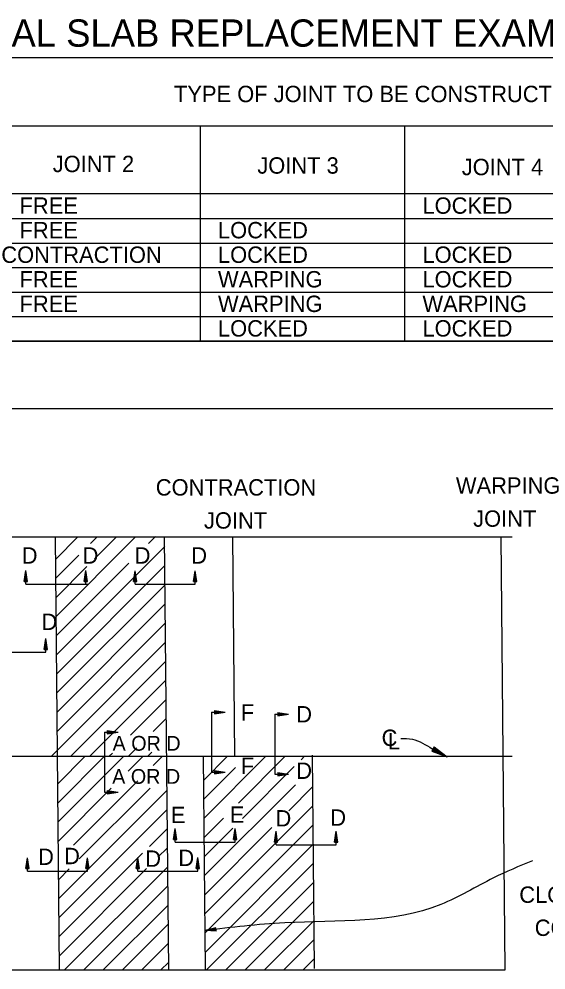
# Model space of a CAD drawing. Extents: x 1375738 to 1375905, y 380661 to 380875.
# Drawn here: x 1375824.96 to 1375840.42, y 380818.56 to 380846.45 of the extents above; entities that cross this region are included whole.
import ezdxf

# ---------------------------------------------------------------- set-up
doc = ezdxf.new("R2010")
doc.units = 0
doc.layers.add('R_Border', color=7, linetype='Continuous')
doc.layers.add('R_Draft', color=7, linetype='Continuous')

msp = doc.modelspace()

# ---------------------------------------------------------------- linework, layer by layer
at = {"layer": 'R_Border'}
msp.add_line((1375786.095, 380835.027), (1375854.78, 380835.027), dxfattribs=at)
at = {"layer": 'R_Draft'}
for p, q in [((1375810.272, 380845.32), (1375854.272, 380845.32)), ((1375818.272, 380843.319), (1375854.272, 380843.319)), ((1375830.272, 380843.319), (1375830.272, 380841.32)), ((1375836.272, 380843.319), (1375836.272, 380841.32)), ((1375830.272, 380841.32), (1375824.272, 380841.32)), ((1375836.272, 380841.32), (1375830.272, 380841.32)), ((1375830.272, 380841.32), (1375830.272, 380840.6)), ((1375842.272, 380841.32), (1375836.272, 380841.32)), ((1375836.272, 380841.32), (1375836.272, 380840.6)), ((1375824.272, 380840.6), (1375830.272, 380840.6)), ((1375830.272, 380840.6), (1375836.272, 380840.6)), ((1375830.272, 380840.6), (1375830.272, 380839.88)), ((1375836.272, 380840.6), (1375836.272, 380839.88)), ((1375836.272, 380840.6), (1375842.272, 380840.6)), ((1375824.272, 380839.88), (1375830.272, 380839.88)), ((1375830.272, 380839.88), (1375830.272, 380839.16)), ((1375830.272, 380839.88), (1375836.272, 380839.88)), ((1375836.272, 380839.88), (1375842.272, 380839.88)), ((1375836.272, 380839.88), (1375836.272, 380839.16)), ((1375824.272, 380839.16), (1375830.272, 380839.16)), ((1375830.272, 380839.16), (1375836.272, 380839.16)), ((1375830.272, 380839.16), (1375830.272, 380838.44)), ((1375836.272, 380839.16), (1375836.272, 380838.44)), ((1375836.272, 380839.16), (1375842.272, 380839.16)), ((1375824.272, 380838.44), (1375830.272, 380838.44)), ((1375830.272, 380838.44), (1375836.272, 380838.44)), ((1375830.272, 380838.44), (1375830.272, 380837.72)), ((1375836.272, 380838.44), (1375836.272, 380837.72)), ((1375836.272, 380838.44), (1375842.272, 380838.44)), ((1375824.272, 380837.72), (1375830.272, 380837.72)), ((1375830.272, 380837.72), (1375830.272, 380837)), ((1375830.272, 380837.72), (1375836.272, 380837.72)), ((1375836.272, 380837.72), (1375836.272, 380837)), ((1375836.272, 380837.72), (1375842.272, 380837.72)), ((1375854.272, 380837), (1375810.272, 380837)), ((1375824.272, 380837), (1375830.272, 380837)), ((1375830.272, 380837), (1375836.272, 380837)), ((1375836.272, 380837), (1375842.272, 380837)), ((1375795.429, 380831.261), (1375839.429, 380831.261)), ((1375826.149, 380818.564), (1375826.027, 380831.261)), ((1375826.034, 380830.611), (1375826.683, 380831.261)), ((1375826.05, 380828.93), (1375828.38, 380831.261)), ((1375827.059, 380831.07), (1375827.249, 380831.261)), ((1375827.174, 380830.62), (1375827.815, 380831.261)), ((1375828.753, 380831.067), (1375828.958, 380831.273)), ((1375829.349, 380818.564), (1375829.228, 380831.261)), ((1375831.289, 380824.829), (1375831.228, 380831.261)), ((1375839.223, 380818.564), (1375839.103, 380831.261)), ((1375826.061, 380827.809), (1375829.231, 380830.979)), ((1375826.039, 380830.051), (1375826.714, 380830.725)), ((1375826.055, 380828.37), (1375828.178, 380830.493)), ((1375826.066, 380827.249), (1375829.236, 380830.419)), ((1375825.109, 380829.954), (1375825.157, 380830.274)), ((1375825.117, 380829.954), (1375825.157, 380830.221)), ((1375825.125, 380829.954), (1375825.157, 380830.166)), ((1375825.157, 380829.874), (1375825.157, 380830.274)), ((1375825.205, 380829.954), (1375825.157, 380830.274)), ((1375825.197, 380829.954), (1375825.157, 380830.221)), ((1375825.189, 380829.954), (1375825.157, 380830.166)), ((1375826.044, 380829.49), (1375826.945, 380830.391)), ((1375826.871, 380829.954), (1375826.919, 380830.274)), ((1375826.879, 380829.954), (1375826.919, 380830.221)), ((1375826.887, 380829.954), (1375826.919, 380830.166)), ((1375826.919, 380829.874), (1375826.919, 380830.274)), ((1375826.967, 380829.954), (1375826.919, 380830.274)), ((1375826.959, 380829.954), (1375826.919, 380830.221)), ((1375826.951, 380829.954), (1375826.919, 380830.166)), ((1375828.319, 380829.952), (1375828.367, 380830.272)), ((1375828.327, 380829.952), (1375828.367, 380830.219)), ((1375828.335, 380829.952), (1375828.367, 380830.164)), ((1375828.367, 380829.872), (1375828.367, 380830.272)), ((1375828.415, 380829.952), (1375828.367, 380830.272)), ((1375828.407, 380829.952), (1375828.367, 380830.219)), ((1375828.399, 380829.952), (1375828.367, 380830.164)), ((1375830.081, 380829.952), (1375830.129, 380830.272)), ((1375830.089, 380829.952), (1375830.129, 380830.219)), ((1375830.097, 380829.952), (1375830.129, 380830.164)), ((1375830.129, 380829.872), (1375830.129, 380830.272)), ((1375830.177, 380829.952), (1375830.129, 380830.272)), ((1375830.169, 380829.952), (1375830.129, 380830.219)), ((1375830.161, 380829.952), (1375830.129, 380830.164)), ((1375825.109, 380829.954), (1375825.205, 380829.954)), ((1375825.133, 380829.954), (1375825.157, 380830.113)), ((1375825.141, 380829.954), (1375825.157, 380830.058)), ((1375825.149, 380829.954), (1375825.157, 380830.005)), ((1375825.181, 380829.954), (1375825.157, 380830.113)), ((1375825.173, 380829.954), (1375825.157, 380830.058)), ((1375825.165, 380829.954), (1375825.157, 380830.005)), ((1375825.157, 380829.874), (1375826.994, 380829.874)), ((1375826.071, 380826.688), (1375829.241, 380829.859)), ((1375826.871, 380829.954), (1375826.967, 380829.954)), ((1375826.895, 380829.954), (1375826.919, 380830.113)), ((1375826.903, 380829.954), (1375826.919, 380830.058)), ((1375826.911, 380829.954), (1375826.919, 380830.005)), ((1375826.943, 380829.954), (1375826.919, 380830.113)), ((1375826.934, 380829.954), (1375826.919, 380830.058)), ((1375826.926, 380829.954), (1375826.919, 380830.005)), ((1375828.319, 380829.952), (1375828.415, 380829.952)), ((1375828.343, 380829.952), (1375828.367, 380830.111)), ((1375828.351, 380829.952), (1375828.367, 380830.056)), ((1375828.359, 380829.952), (1375828.367, 380830.003)), ((1375828.391, 380829.952), (1375828.367, 380830.111)), ((1375828.383, 380829.952), (1375828.367, 380830.056)), ((1375828.375, 380829.952), (1375828.367, 380830.003)), ((1375828.367, 380829.872), (1375830.129, 380829.872)), ((1375830.081, 380829.952), (1375830.177, 380829.952)), ((1375830.105, 380829.952), (1375830.129, 380830.111)), ((1375830.113, 380829.952), (1375830.129, 380830.056)), ((1375830.121, 380829.952), (1375830.129, 380830.003)), ((1375830.153, 380829.952), (1375830.129, 380830.111)), ((1375830.144, 380829.952), (1375830.129, 380830.056)), ((1375830.136, 380829.952), (1375830.129, 380830.003)), ((1375826.077, 380826.128), (1375829.247, 380829.298)), ((1375826.082, 380825.568), (1375829.252, 380828.738)), ((1375825.699, 380827.963), (1375825.747, 380828.283)), ((1375825.707, 380827.963), (1375825.747, 380828.229)), ((1375825.715, 380827.963), (1375825.747, 380828.175)), ((1375825.747, 380827.883), (1375825.747, 380828.283)), ((1375825.795, 380827.963), (1375825.747, 380828.283)), ((1375825.787, 380827.963), (1375825.747, 380828.229)), ((1375825.779, 380827.963), (1375825.747, 380828.175)), ((1375825.909, 380824.829), (1375829.257, 380828.178)), ((1375825.699, 380827.963), (1375825.795, 380827.963)), ((1375825.723, 380827.963), (1375825.747, 380828.121)), ((1375825.731, 380827.963), (1375825.747, 380828.067)), ((1375825.739, 380827.963), (1375825.747, 380828.013)), ((1375825.771, 380827.963), (1375825.747, 380828.121)), ((1375825.762, 380827.963), (1375825.747, 380828.067)), ((1375825.754, 380827.963), (1375825.747, 380828.013)), ((1375823.985, 380827.883), (1375825.747, 380827.883)), ((1375826.475, 380824.829), (1375829.263, 380827.617)), ((1375827.04, 380824.829), (1375829.268, 380827.057)), ((1375828.229, 380825.452), (1375829.273, 380826.497)), ((1375830.61, 380826.123), (1375830.61, 380824.361)), ((1375830.61, 380826.123), (1375831.01, 380826.123)), ((1375830.69, 380826.171), (1375831.01, 380826.123)), ((1375830.69, 380826.171), (1375830.69, 380826.075)), ((1375830.69, 380826.163), (1375830.957, 380826.123)), ((1375830.69, 380826.155), (1375830.902, 380826.123)), ((1375830.69, 380826.147), (1375830.849, 380826.123)), ((1375830.69, 380826.138), (1375830.794, 380826.123)), ((1375830.69, 380826.13), (1375830.741, 380826.123)), ((1375830.69, 380826.075), (1375831.01, 380826.123)), ((1375830.69, 380826.107), (1375830.794, 380826.123)), ((1375830.69, 380826.091), (1375830.902, 380826.123)), ((1375830.69, 380826.083), (1375830.957, 380826.123)), ((1375830.69, 380826.099), (1375830.849, 380826.123)), ((1375830.69, 380826.115), (1375830.741, 380826.123)), ((1375832.467, 380826.064), (1375832.467, 380824.302)), ((1375832.467, 380826.064), (1375832.867, 380826.064)), ((1375832.547, 380826.112), (1375832.867, 380826.064)), ((1375832.547, 380826.112), (1375832.547, 380826.016)), ((1375832.547, 380826.104), (1375832.813, 380826.064)), ((1375832.547, 380826.096), (1375832.759, 380826.064)), ((1375832.547, 380826.088), (1375832.705, 380826.064)), ((1375832.547, 380826.079), (1375832.651, 380826.064)), ((1375832.547, 380826.071), (1375832.597, 380826.064)), ((1375832.547, 380826.016), (1375832.867, 380826.064)), ((1375832.547, 380826.048), (1375832.651, 380826.064)), ((1375832.547, 380826.032), (1375832.759, 380826.064)), ((1375832.547, 380826.024), (1375832.813, 380826.064)), ((1375832.547, 380826.04), (1375832.705, 380826.064)), ((1375832.547, 380826.056), (1375832.597, 380826.064)), ((1375828.898, 380825.556), (1375829.279, 380825.937)), ((1375827.465, 380825.539), (1375827.465, 380823.777)), ((1375827.465, 380825.539), (1375827.865, 380825.539)), ((1375827.545, 380825.587), (1375827.865, 380825.539)), ((1375827.545, 380825.587), (1375827.545, 380825.491)), ((1375827.545, 380825.579), (1375827.812, 380825.539)), ((1375827.545, 380825.571), (1375827.757, 380825.539)), ((1375827.545, 380825.563), (1375827.704, 380825.539)), ((1375827.545, 380825.555), (1375827.649, 380825.539)), ((1375827.545, 380825.547), (1375827.596, 380825.539)), ((1375827.545, 380825.491), (1375827.865, 380825.539)), ((1375827.545, 380825.523), (1375827.649, 380825.539)), ((1375827.545, 380825.507), (1375827.757, 380825.539)), ((1375827.545, 380825.499), (1375827.812, 380825.539)), ((1375827.545, 380825.515), (1375827.704, 380825.539)), ((1375827.545, 380825.531), (1375827.596, 380825.539)), ((1375794.677, 380824.829), (1375839.429, 380824.829)), ((1375806.196, 380824.829), (1375839.375, 380824.829)), ((1375826.097, 380824.023), (1375826.903, 380824.829)), ((1375826.102, 380823.463), (1375827.469, 380824.829)), ((1375826.107, 380822.903), (1375828.034, 380824.829)), ((1375827.606, 380824.829), (1375827.696, 380824.92)), ((1375828.162, 380824.391), (1375828.6, 380824.829)), ((1375828.171, 380824.829), (1375828.418, 380825.075)), ((1375828.738, 380824.829), (1375828.857, 380824.949)), ((1375828.894, 380824.558), (1375829.165, 380824.829)), ((1375830.429, 380818.574), (1375830.369, 380824.829)), ((1375830.376, 380824.133), (1375831.072, 380824.829)), ((1375830.387, 380823.013), (1375832.203, 380824.829)), ((1375831.395, 380823.455), (1375832.769, 380824.829)), ((1375833.233, 380824.728), (1375833.335, 380824.829)), ((1375833.629, 380818.605), (1375833.569, 380824.86)), ((1375837.137, 380825.102), (1375837.068, 380824.975)), ((1375837.068, 380824.975), (1375837.524, 380824.809)), ((1375837.074, 380824.986), (1375837.453, 380824.847)), ((1375837.079, 380824.997), (1375837.381, 380824.887)), ((1375837.085, 380825.007), (1375837.311, 380824.925)), ((1375837.091, 380825.018), (1375837.239, 380824.964)), ((1375837.097, 380825.029), (1375837.169, 380825.002)), ((1375837.108, 380825.049), (1375837.169, 380825.002)), ((1375837.113, 380825.059), (1375837.239, 380824.964)), ((1375837.119, 380825.07), (1375837.311, 380824.925)), ((1375837.125, 380825.081), (1375837.381, 380824.887)), ((1375837.131, 380825.091), (1375837.453, 380824.847)), ((1375837.137, 380825.102), (1375837.524, 380824.809)), ((1375830.381, 380823.573), (1375831.309, 380824.501)), ((1375830.61, 380824.361), (1375831.01, 380824.361)), ((1375830.69, 380824.409), (1375831.01, 380824.361)), ((1375830.69, 380824.409), (1375830.69, 380824.313)), ((1375830.69, 380824.401), (1375830.957, 380824.361)), ((1375830.69, 380824.393), (1375830.902, 380824.361)), ((1375830.69, 380824.385), (1375830.849, 380824.361)), ((1375830.69, 380824.377), (1375830.794, 380824.361)), ((1375830.69, 380824.369), (1375830.741, 380824.361)), ((1375830.69, 380824.313), (1375831.01, 380824.361)), ((1375830.69, 380824.345), (1375830.794, 380824.361)), ((1375830.69, 380824.329), (1375830.902, 380824.361)), ((1375830.69, 380824.321), (1375830.957, 380824.361)), ((1375830.69, 380824.337), (1375830.849, 380824.361)), ((1375830.69, 380824.353), (1375830.741, 380824.361)), ((1375831.511, 380823.005), (1375833.035, 380824.529)), ((1375832.467, 380824.302), (1375832.867, 380824.302)), ((1375832.547, 380824.35), (1375832.867, 380824.302)), ((1375832.547, 380824.35), (1375832.547, 380824.254)), ((1375832.547, 380824.342), (1375832.813, 380824.302)), ((1375832.547, 380824.334), (1375832.759, 380824.302)), ((1375832.547, 380824.326), (1375832.705, 380824.302)), ((1375832.547, 380824.318), (1375832.651, 380824.302)), ((1375832.547, 380824.31), (1375832.597, 380824.302)), ((1375832.547, 380824.254), (1375832.867, 380824.302)), ((1375832.547, 380824.287), (1375832.651, 380824.302)), ((1375832.547, 380824.27), (1375832.759, 380824.302)), ((1375832.547, 380824.262), (1375832.813, 380824.302)), ((1375832.547, 380824.278), (1375832.705, 380824.302)), ((1375832.547, 380824.295), (1375832.597, 380824.302)), ((1375826.555, 380822.219), (1375828.445, 380824.109)), ((1375830.403, 380821.331), (1375833.067, 380823.996)), ((1375826.113, 380822.343), (1375827.661, 380823.89)), ((1375826.129, 380820.661), (1375829.299, 380823.831)), ((1375826.724, 380821.821), (1375828.801, 380823.899)), ((1375827.465, 380823.777), (1375827.865, 380823.777)), ((1375827.545, 380823.825), (1375827.865, 380823.777)), ((1375827.545, 380823.825), (1375827.545, 380823.729)), ((1375827.545, 380823.817), (1375827.812, 380823.777)), ((1375827.545, 380823.809), (1375827.757, 380823.777)), ((1375827.545, 380823.801), (1375827.704, 380823.777)), ((1375827.545, 380823.793), (1375827.649, 380823.777)), ((1375827.545, 380823.785), (1375827.596, 380823.777)), ((1375827.545, 380823.729), (1375827.865, 380823.777)), ((1375827.545, 380823.762), (1375827.649, 380823.777)), ((1375827.545, 380823.745), (1375827.757, 380823.777)), ((1375827.545, 380823.737), (1375827.812, 380823.777)), ((1375827.545, 380823.753), (1375827.704, 380823.777)), ((1375827.545, 380823.77), (1375827.596, 380823.777)), ((1375832.87, 380823.233), (1375833.578, 380823.941)), ((1375826.134, 380820.101), (1375829.304, 380823.271)), ((1375830.414, 380820.211), (1375833.583, 380823.381)), ((1375830.392, 380822.453), (1375830.957, 380823.017)), ((1375828.783, 380822.183), (1375829.31, 380822.711)), ((1375829.494, 380822.388), (1375829.542, 380822.708)), ((1375829.502, 380822.388), (1375829.542, 380822.655)), ((1375829.51, 380822.388), (1375829.542, 380822.6)), ((1375829.542, 380822.308), (1375829.542, 380822.708)), ((1375829.59, 380822.388), (1375829.542, 380822.708)), ((1375829.582, 380822.388), (1375829.542, 380822.655)), ((1375829.574, 380822.388), (1375829.542, 380822.6)), ((1375830.397, 380821.892), (1375831.229, 380822.723)), ((1375830.408, 380820.771), (1375832.379, 380822.742)), ((1375830.419, 380819.651), (1375833.589, 380822.821)), ((1375831.255, 380822.388), (1375831.303, 380822.708)), ((1375831.263, 380822.388), (1375831.303, 380822.655)), ((1375831.271, 380822.388), (1375831.303, 380822.6)), ((1375831.303, 380822.308), (1375831.303, 380822.708)), ((1375831.351, 380822.388), (1375831.303, 380822.708)), ((1375831.343, 380822.388), (1375831.303, 380822.655)), ((1375831.335, 380822.388), (1375831.303, 380822.6)), ((1375832.45, 380822.312), (1375832.498, 380822.632)), ((1375832.498, 380822.232), (1375832.498, 380822.632)), ((1375832.546, 380822.312), (1375832.498, 380822.632)), ((1375834.211, 380822.312), (1375834.259, 380822.632)), ((1375834.259, 380822.232), (1375834.259, 380822.632)), ((1375834.307, 380822.312), (1375834.259, 380822.632)), ((1375829.494, 380822.388), (1375829.59, 380822.388)), ((1375829.518, 380822.388), (1375829.542, 380822.547)), ((1375829.526, 380822.388), (1375829.542, 380822.492)), ((1375829.534, 380822.388), (1375829.542, 380822.439)), ((1375829.566, 380822.388), (1375829.542, 380822.547)), ((1375829.557, 380822.388), (1375829.542, 380822.492)), ((1375829.549, 380822.388), (1375829.542, 380822.439)), ((1375831.255, 380822.388), (1375831.351, 380822.388)), ((1375831.279, 380822.388), (1375831.303, 380822.547)), ((1375831.288, 380822.388), (1375831.303, 380822.492)), ((1375831.296, 380822.388), (1375831.303, 380822.439)), ((1375831.327, 380822.388), (1375831.303, 380822.547)), ((1375831.319, 380822.388), (1375831.303, 380822.492)), ((1375831.311, 380822.388), (1375831.303, 380822.439)), ((1375832.458, 380822.312), (1375832.498, 380822.579)), ((1375832.466, 380822.312), (1375832.498, 380822.524)), ((1375832.474, 380822.312), (1375832.498, 380822.471)), ((1375832.482, 380822.312), (1375832.498, 380822.416)), ((1375832.49, 380822.312), (1375832.498, 380822.363)), ((1375832.538, 380822.312), (1375832.498, 380822.579)), ((1375832.53, 380822.312), (1375832.498, 380822.524)), ((1375832.522, 380822.312), (1375832.498, 380822.471)), ((1375832.513, 380822.312), (1375832.498, 380822.416)), ((1375832.505, 380822.312), (1375832.498, 380822.363)), ((1375834.219, 380822.312), (1375834.259, 380822.579)), ((1375834.227, 380822.312), (1375834.259, 380822.524)), ((1375834.235, 380822.312), (1375834.259, 380822.471)), ((1375834.244, 380822.312), (1375834.259, 380822.416)), ((1375834.252, 380822.312), (1375834.259, 380822.363)), ((1375834.299, 380822.312), (1375834.259, 380822.579)), ((1375834.291, 380822.312), (1375834.259, 380822.524)), ((1375834.283, 380822.312), (1375834.259, 380822.471)), ((1375834.275, 380822.312), (1375834.259, 380822.416)), ((1375834.267, 380822.312), (1375834.259, 380822.363)), ((1375829.035, 380821.869), (1375829.315, 380822.15)), ((1375829.542, 380822.308), (1375831.303, 380822.308)), ((1375830.425, 380819.091), (1375833.594, 380822.26)), ((1375832.45, 380822.312), (1375832.546, 380822.312)), ((1375832.498, 380822.232), (1375834.259, 380822.232)), ((1375834.211, 380822.312), (1375834.307, 380822.312)), ((1375825.157, 380821.537), (1375825.205, 380821.857)), ((1375825.165, 380821.537), (1375825.205, 380821.803)), ((1375825.205, 380821.457), (1375825.205, 380821.857)), ((1375825.253, 380821.537), (1375825.205, 380821.857)), ((1375825.245, 380821.537), (1375825.205, 380821.803)), ((1375826.14, 380819.541), (1375828.585, 380821.985)), ((1375826.919, 380821.537), (1375826.967, 380821.857)), ((1375826.927, 380821.537), (1375826.967, 380821.803)), ((1375826.967, 380821.457), (1375826.967, 380821.857)), ((1375827.015, 380821.537), (1375826.967, 380821.857)), ((1375827.007, 380821.537), (1375826.967, 380821.803)), ((1375828.397, 380821.542), (1375828.445, 380821.862)), ((1375828.405, 380821.542), (1375828.445, 380821.808)), ((1375828.445, 380821.462), (1375828.445, 380821.862)), ((1375828.493, 380821.542), (1375828.445, 380821.862)), ((1375828.485, 380821.542), (1375828.445, 380821.808)), ((1375830.158, 380821.542), (1375830.206, 380821.862)), ((1375830.166, 380821.542), (1375830.206, 380821.808)), ((1375830.206, 380821.462), (1375830.206, 380821.862)), ((1375830.254, 380821.542), (1375830.206, 380821.862)), ((1375830.246, 380821.542), (1375830.206, 380821.808)), ((1375825.157, 380821.537), (1375825.253, 380821.537)), ((1375825.173, 380821.537), (1375825.205, 380821.749)), ((1375825.181, 380821.537), (1375825.205, 380821.695)), ((1375825.189, 380821.537), (1375825.205, 380821.641)), ((1375825.197, 380821.537), (1375825.205, 380821.587)), ((1375825.237, 380821.537), (1375825.205, 380821.749)), ((1375825.229, 380821.537), (1375825.205, 380821.695)), ((1375825.221, 380821.537), (1375825.205, 380821.641)), ((1375825.213, 380821.537), (1375825.205, 380821.587)), ((1375826.123, 380821.221), (1375826.431, 380821.529)), ((1375826.145, 380818.98), (1375828.701, 380821.535)), ((1375826.294, 380818.564), (1375829.321, 380821.59)), ((1375826.919, 380821.537), (1375827.015, 380821.537)), ((1375826.935, 380821.537), (1375826.967, 380821.749)), ((1375826.943, 380821.537), (1375826.967, 380821.695)), ((1375826.951, 380821.537), (1375826.967, 380821.641)), ((1375826.959, 380821.537), (1375826.967, 380821.587)), ((1375826.999, 380821.537), (1375826.967, 380821.749)), ((1375826.991, 380821.537), (1375826.967, 380821.695)), ((1375826.982, 380821.537), (1375826.967, 380821.641)), ((1375826.974, 380821.537), (1375826.967, 380821.587)), ((1375828.397, 380821.542), (1375828.493, 380821.542)), ((1375828.413, 380821.542), (1375828.445, 380821.753)), ((1375828.421, 380821.542), (1375828.445, 380821.7)), ((1375828.429, 380821.542), (1375828.445, 380821.646)), ((1375828.437, 380821.542), (1375828.445, 380821.592)), ((1375828.477, 380821.542), (1375828.445, 380821.753)), ((1375828.469, 380821.542), (1375828.445, 380821.7)), ((1375828.46, 380821.542), (1375828.445, 380821.646)), ((1375828.452, 380821.542), (1375828.445, 380821.592)), ((1375830.158, 380821.542), (1375830.254, 380821.542)), ((1375830.174, 380821.542), (1375830.206, 380821.753)), ((1375830.182, 380821.542), (1375830.206, 380821.7)), ((1375830.191, 380821.542), (1375830.206, 380821.646)), ((1375830.199, 380821.542), (1375830.206, 380821.592)), ((1375830.238, 380821.542), (1375830.206, 380821.753)), ((1375830.23, 380821.542), (1375830.206, 380821.7)), ((1375830.222, 380821.542), (1375830.206, 380821.646)), ((1375830.214, 380821.542), (1375830.206, 380821.592)), ((1375830.463, 380818.564), (1375833.6, 380821.7)), ((1375825.205, 380821.457), (1375826.967, 380821.457)), ((1375828.445, 380821.462), (1375830.206, 380821.462)), ((1375826.86, 380818.564), (1375829.326, 380821.03)), ((1375831.029, 380818.564), (1375833.605, 380821.14)), ((1375827.425, 380818.564), (1375829.331, 380820.469)), ((1375831.595, 380818.564), (1375833.611, 380820.58)), ((1375827.991, 380818.564), (1375829.337, 380819.909)), ((1375832.16, 380818.564), (1375833.616, 380820.019)), ((1375830.73, 380819.8), (1375830.416, 380819.721)), ((1375830.739, 380819.704), (1375830.416, 380819.721)), ((1375830.731, 380819.792), (1375830.469, 380819.727)), ((1375830.738, 380819.712), (1375830.469, 380819.727)), ((1375830.731, 380819.784), (1375830.524, 380819.732)), ((1375830.737, 380819.72), (1375830.524, 380819.732)), ((1375830.732, 380819.776), (1375830.577, 380819.737)), ((1375830.737, 380819.728), (1375830.577, 380819.737)), ((1375830.733, 380819.767), (1375830.631, 380819.742)), ((1375830.736, 380819.737), (1375830.631, 380819.742)), ((1375830.734, 380819.759), (1375830.684, 380819.747)), ((1375830.735, 380819.745), (1375830.684, 380819.747)), ((1375830.739, 380819.704), (1375830.73, 380819.8)), ((1375828.557, 380818.564), (1375829.342, 380819.349)), ((1375832.726, 380818.564), (1375833.621, 380819.459)), ((1375829.123, 380818.564), (1375829.347, 380818.788)), ((1375833.292, 380818.564), (1375833.627, 380818.898)), ((1375795.429, 380818.564), (1375839.223, 380818.564))]:
    msp.add_line(p, q, dxfattribs=at)
for points in [[(1375836.156, 380825.352), (1375836.498, 380825.332), (1375837.081, 380825.05), (1375837.524, 380824.809)], [(1375840.02, 380821.766), (1375838.875, 380821.261), (1375837.337, 380820.486), (1375832.753, 380819.946), (1375830.416, 380819.721)]]:
    msp.add_spline(points, degree=3, dxfattribs=at)

# ---------------------------------------------------------------- texts
for s, height, p in [('TYPICAL SLAB REPLACEMENT EXAMPLES', 0.7996, (1375821.587, 380845.636)), ('TYPE OF JOINT TO BE CONSTRUCTED', 0.48, (1375829.505, 380844.01)), ('JOINT 2', 0.48, (1375825.947, 380841.958)), ('JOINT 3', 0.48, (1375831.95, 380841.913)), ('JOINT 4', 0.48, (1375837.948, 380841.868)), ('   FREE    ', 0.48, (1375824.438, 380840.737)), ('  LOCKED   ', 0.48, (1375836.438, 380840.737)), ('   FREE    ', 0.48, (1375824.438, 380840.017)), ('  LOCKED   ', 0.48, (1375830.438, 380840.017)), ('CONTRACTION', 0.48, (1375824.438, 380839.297)), ('  LOCKED   ', 0.48, (1375830.438, 380839.297)), ('  LOCKED   ', 0.48, (1375836.438, 380839.297)), ('   FREE    ', 0.48, (1375824.438, 380838.577)), ('  WARPING  ', 0.48, (1375830.438, 380838.577)), ('  LOCKED   ', 0.48, (1375836.438, 380838.577)), ('   FREE    ', 0.48, (1375824.438, 380837.857)), ('  WARPING  ', 0.48, (1375830.438, 380837.857)), ('  WARPING  ', 0.48, (1375836.438, 380837.857)), ('  LOCKED   ', 0.48, (1375830.438, 380837.137)), ('  LOCKED   ', 0.48, (1375836.438, 380837.137)), ('CONTRACTION', 0.48, (1375828.97, 380832.475)), ('WARPING', 0.48, (1375837.776, 380832.529)), ('JOINT', 0.48, (1375830.384, 380831.505)), ('JOINT', 0.48, (1375838.282, 380831.559)), ('D', 0.48, (1375825.038, 380830.478)), ('D', 0.48, (1375826.822, 380830.478)), ('D', 0.48, (1375828.35, 380830.478)), ('D', 0.48, (1375830.011, 380830.478)), ('D', 0.48, (1375825.617, 380828.532)), ('F', 0.48, (1375831.466, 380825.877)), ('D', 0.48, (1375833.091, 380825.822)), ('A OR D', 0.4332, (1375827.703, 380824.993)), ('C', 0.48, (1375835.596, 380825.132)), ('L', 0.48, (1375835.778, 380825.029)), ('F', 0.48, (1375831.466, 380824.309)), ('D', 0.48, (1375833.091, 380824.167)), ('A OR D', 0.4332, (1375827.691, 380824.022)), ('E', 0.48, (1375829.413, 380822.871)), ('E', 0.48, (1375831.141, 380822.879)), ('D', 0.48, (1375832.482, 380822.771)), ('D', 0.48, (1375834.09, 380822.793)), ('D', 0.48, (1375825.516, 380821.643)), ('D', 0.48, (1375826.281, 380821.666)), ('D', 0.48, (1375828.66, 380821.589)), ('D', 0.48, (1375829.633, 380821.612)), ('CLOSEST TO EXISTING', 0.48, (1375839.636, 380820.532)), ('CONTRACTION JOINT', 0.48, (1375840.089, 380819.562))]:
    msp.add_text(s, height=height, dxfattribs=at).set_placement(p)

doc.saveas('drawing.dxf')
